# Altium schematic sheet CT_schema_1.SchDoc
size 465 x 258 mm
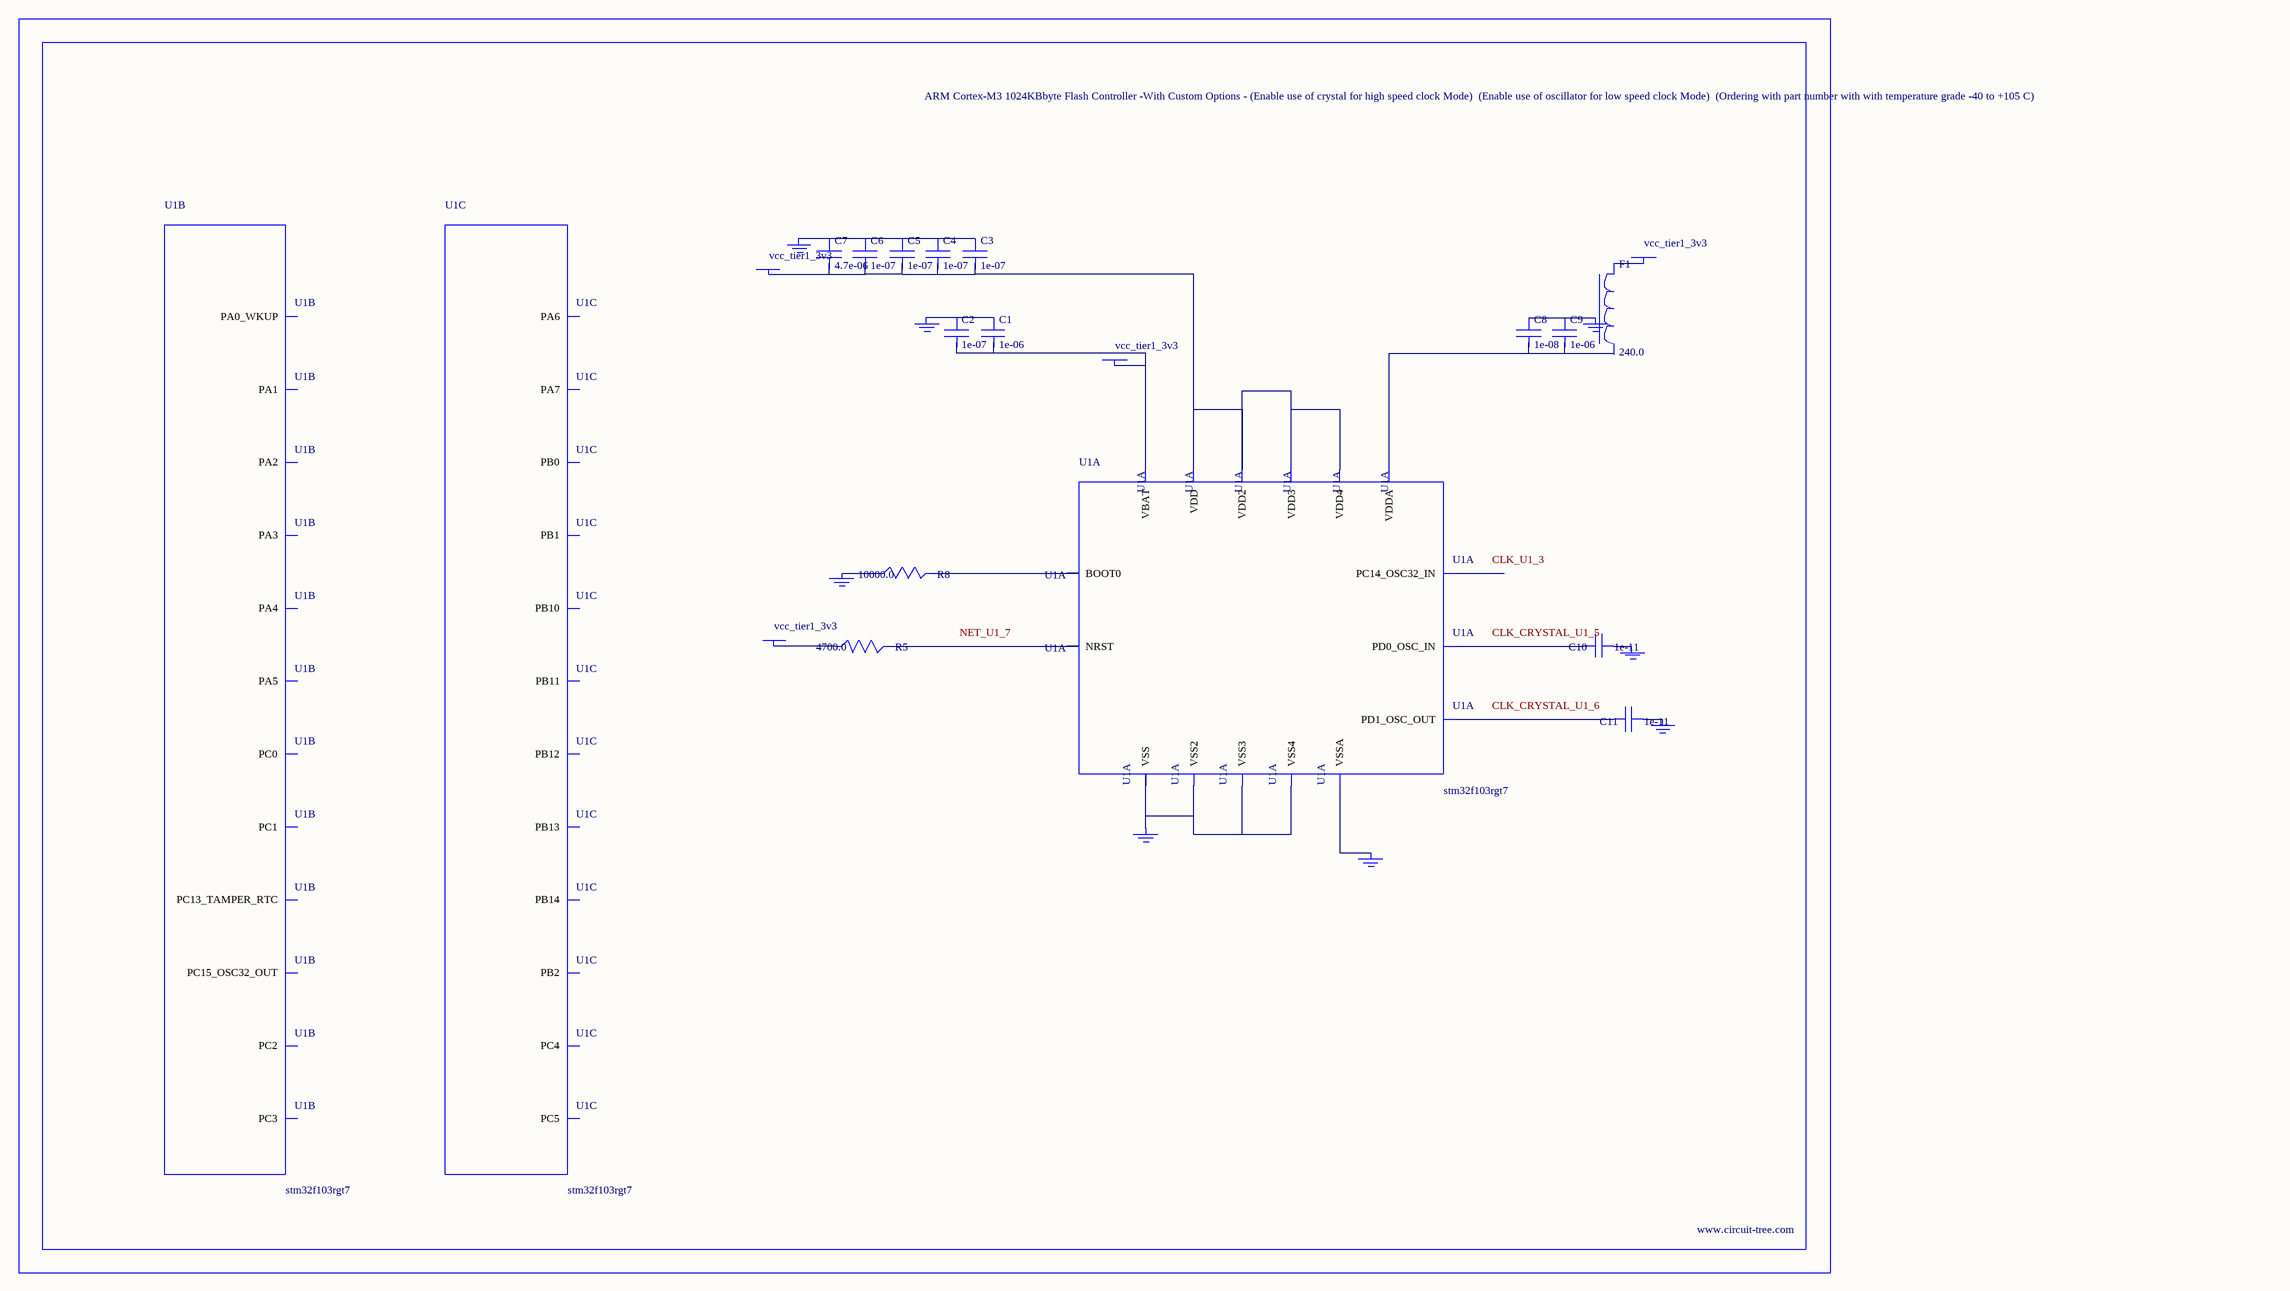
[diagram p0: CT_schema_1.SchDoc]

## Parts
BORDER0  (no value)
C1  1e-06  [C0603]
C2  1e-07  [C0603]
C3  1e-07  [C0603]
C4  1e-07  [C0603]
C5  1e-07  [C0603]
C6  1e-07  [C0603]
C7  4.7e-06  [C0603]
C8  1e-08  [C0603]
C9  1e-06  [C0603]
C10  1e-11  [C0402]
C11  1e-11  [C0402]
F1  240.0  [L0603]
GND_INSTANCE_0_0  (no value)
GND_INSTANCE_0_1  (no value)
GND_INSTANCE_0_2  (no value)
GND_INSTANCE_0_3  (no value)
GND_INSTANCE_0_4  (no value)
GND_INSTANCE_0_5  (no value)
GND_INSTANCE_0_6  (no value)
GND_INSTANCE_0_7  (no value)
POWER_INSTANCE_0_0  vcc_tier1_3v3
POWER_INSTANCE_0_1  vcc_tier1_3v3
POWER_INSTANCE_0_2  vcc_tier1_3v3
POWER_INSTANCE_0_3  vcc_tier1_3v3
R5  4700.0  [R0603]
R8  10000.0  [R0603]
U1  stm32f103rgt7  [LQFP64]  (parts A,B,C of 6)

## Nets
NetC1_1: C1.1 C2.1 GND_INSTANCE_0_0.0(GND)
NetC1_2: C1.2 C2.2 POWER_INSTANCE_0_0.0(PWR) U1.1(VBAT)
NetC3_1: C3.1 C4.1 C5.1 C6.1 C7.1 GND_INSTANCE_0_5.0(GND)
NetC3_2: C3.2 C4.2 C5.2 C6.2 C7.2 POWER_INSTANCE_0_2.0(PWR) U1.19(VDD) U1.32(VDD2) U1.48(VDD3) U1.64(VDD4)
NetC8_1: C8.1 C9.1 GND_INSTANCE_0_4.0(GND)
NetC8_2: C8.2 C9.2 U1.13(VDDA)
NetC10_1: C10.1 GND_INSTANCE_0_1.0(GND)
NetC10_2: C10.2 U1.5(PD0_OSC_IN)
NetC11_1: C11.1 GND_INSTANCE_0_2.0(GND)
NetC11_2: C11.2 U1.6(PD1_OSC_OUT)
NetF1_1: F1.1 POWER_INSTANCE_0_1.0(PWR)
NetGND_INSTANCE_0_3_0: GND_INSTANCE_0_3.0(GND) U1.12(VSSA)
NetGND_INSTANCE_0_6_0: GND_INSTANCE_0_6.0(GND) R8.1
NetGND_INSTANCE_0_7_0: GND_INSTANCE_0_7.0(GND) U1.18(VSS) U1.31(VSS2) U1.47(VSS3) U1.63(VSS4)
NetPOWER_INSTANCE_0_3_0: POWER_INSTANCE_0_3.0(PWR) R5.1
NetR5_2: R5.2 U1.7(NRST)
NetR8_2: R8.2 U1.60(BOOT0)

Not connected (* = marked no-connect by the designer): F1 2; U1 2(PC13_TAMPER_RTC) 3(PC14_OSC32_IN) 4(PC15_OSC32_OUT) 8(PC0) 9(PC1) 10(PC2) 11(PC3) 14(PA0_WKUP) 15(PA1) 16(PA2) 17(PA3) 20(PA4) 21(PA5) 22(PA6) 23(PA7) 24(PC4) 25(PC5) 26(PB0) 27(PB1) 28(PB2) 29(PB10) 30(PB11) 33(PB12) 34(PB13) 35(PB14)

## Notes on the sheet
- Labels drawn without touching a wire or pin: CLK_CRYSTAL_U1_5, CLK_CRYSTAL_U1_6, CLK_U1_3, NET_U1_7

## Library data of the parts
BORDER0 = BORDER_PAGE0
C1 C9 = C0603C105K3RACTU
C2-C6 = 06035C104K4Z2A
C7 = GRM188R6YA475KE15D
C8 = 06035C103K4Z2A
C10 C11 = C0402C100K3GACTU
F1 = Z0603C241ASMST
GND_INSTANCE_0_0-GND_INSTANCE_0_7 = GND
POWER_INSTANCE_0_0-POWER_INSTANCE_0_3 = PWR
R5 = RC0603JR-074K7L
R8 = RC0603JR-0710KL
